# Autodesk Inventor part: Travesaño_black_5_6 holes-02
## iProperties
Created: 2008-01
Part Number: Travesaño_black_5_6 holes-02
Material: Default
Document SubType Name: Modeling
Designer: eruiz-tagle
Mass: 0.598659 g
Surface Area: 14.944 cm^2
Volume: 0.598659 cm^3
Density: 1 g/cm^3
Author: eruiz-tagle
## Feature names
1. Derived Body1 [Tagging]
